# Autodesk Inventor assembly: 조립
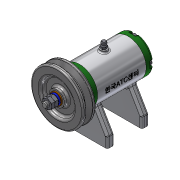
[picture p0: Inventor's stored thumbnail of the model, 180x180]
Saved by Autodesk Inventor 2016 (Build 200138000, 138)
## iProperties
Created: 2018-05
Part Number: 조립
Material: 일반
Document SubType Name: Assembly
Designer: Administrator
Author: Administrator
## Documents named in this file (16)
- C:\Users\Administrator\Desktop\480507V1009\조립.iam
- C:\Users\Administrator\Desktop\480507V1009\본체.ipt
- C:\Users\Administrator\Desktop\480507V1009\축.ipt
- C:\Users\Administrator\Desktop\480507V1009\키 3x3x12.ipt
- C:\Users\Administrator\Desktop\480507V1009\베어링 6002.ipt
- C:\Users\Administrator\Desktop\480507V1009\뒤커버.ipt
- C:\Users\Administrator\Desktop\480507V1009\앞커버.ipt
- C:\Users\Administrator\Desktop\480507V1009\오일 실 15 25 7.ipt
- C:\Users\Administrator\Desktop\480507V1009\볼트 M4x12.ipt
- C:\Users\Administrator\Desktop\480507V1009\볼트 M6x8.ipt
- C:\Users\Administrator\Desktop\480507V1009\와셔 6x11.5.ipt
- C:\Users\Administrator\Desktop\480507V1009\니플 M6x0.75.ipt
- C:\Users\Administrator\Desktop\480507V1009\V벨트풀리.ipt
- C:\Users\Administrator\Desktop\480507V1009\너트 M8.ipt
- C:\Users\Administrator\Desktop\480507V1009\스프링와셔 8.ipt
- C:\Users\Administrator\Desktop\480507V1009\와셔 8x17.ipt
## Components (1 placed, 1 different names)
1. V벨트풀리:1 — 각도:2
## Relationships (1: Angle 1)
- 각도:2 [Angle]: V벨트풀리:1
